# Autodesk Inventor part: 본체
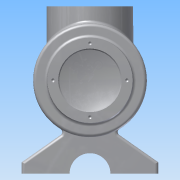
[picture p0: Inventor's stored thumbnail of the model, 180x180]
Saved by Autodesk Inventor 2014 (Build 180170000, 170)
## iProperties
Created: 2017-04
Part Number: 본체
Material: 알루미늄 6061
Document SubType Name: Modeling
Designer: NET
Mass: 1666.1 g
Surface Area: 1068.54 cm^2
Volume: 614.797 cm^3
Density: 2.71 g/cm^3
Appearance: 알루미늄 - 평지
Author: NET
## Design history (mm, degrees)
sketch "스케치1"
  geometry: L1 (-60, -40)-(60, -40); L2 (60, -40)-(60, 40); L3 (60, 40)-(-60, 40); L4 (-60, 40)-(-60, -40); L5 (-60, -40)-(60, 40); L6 (60, -40)-(-60, 40); 1 further point
  constraints: 12 end point, 2 midpoint, 2 parallel, 1 horizontal, 1 perpendicular
  dimensions: "d0" = 120 distance of L3.end L2.end; "d1" = 80 distance of L2.end L1.end
extrude "돌출1" new body sketch "스케치1" distance "d2" = 10; taper "d3" = 0 deg
sketch "스케치2"
  geometry: L1 (60, 0)-(-60, 0) reference; L2 (-60, 0)-(-60, 10) reference; L3 (60, 10)-(-60, 10) reference; L4 (60, 0)-(60, 10) reference; L5 (-60, 10)-(0, 52.012); L6 (-60, 10)-(13.246, 10); L7 (0, 52.012)-(60, 10); 1 further point
  constraints: 6 end point, 1 equal length, 1 horizontal
  dimensions: "d4" = 35 deg angle of L6 L5; "d5" = 35 deg angle of L1 L7
extrude "돌출2" join sketch "스케치2" stored distance "d6" = 80; taper "d7" = 0 deg
sketch "스케치3"
  geometry: C1 r 50 at (0, 82); 1 further point
  constraints: 1 centre point, 1 vertical alignment
  dimensions: "d8" = 100 diameter of C1; "d9" = 82 distance of point (0, 0) C1.centre
extrude "돌출3" join sketch "스케치3" stored distance "d10" = 108; taper "d11" = 0 deg
sketch "스케치4"
  geometry: C1 r 50 at (0, 0) reference; C2 r 37.5 at (0, 0); 1 further point
  constraints: 1 centre point, 1 coincident
  dimensions: "d12" = 75 diameter of C2
extrude "돌출4" join sketch "스케치4" distance "d13" = 12; taper "d14" = 0 deg
sketch "스케치5"
  geometry: L1 (119.5, 66)-(44.5, 66) reference; L2 (32, -54)-(132, -54) reference; L3 (82, 66)-(82, 59); L4 (82, 59)-(82, -54); L5 (82, 59)-(195, 59); L6 (132, -42.336)-(82, -42.336); L7 (82, -54)-(82, -42.336); L8 (132, -42.336)-(132, -54); L9 (82, -54)-(82, -42.336); L10 (132, -54)-(82, -54); 1 further point
  constraints: 16 end point, 4 perpendicular, 2 midpoint, 1 coincident, 1 collinear, 1 horizontal, 1 parallel, 1 point on line
  dimensions: "d18" = 7 distance of L3.start L3.end; "d19" = 90 deg angle of L4 L5; "d20" = 11.66393 distance from line of L2.end L6
revolve "회전1" sketch "스케치5" stored, may be unused: angle "d21" = 90 deg
sketch "스케치6"
  geometry: L1 (119.5, 66)-(44.5, 66) reference; L2 (82, 66)-(82, 59); L3 (82, 59)-(82, -54); L4 (82, 59)-(195, 59); L5 (132, -42.336)-(32, -42.336) reference; L6 (132, -42.336)-(82, -42.336); L7 (82, -54)-(82, -42.336); A1 r 113 centre (82, 59) between (82, -54) and (132, -42.336); 1 further point
  constraints: 10 end point, 2 midpoint, 2 perpendicular, 2 point on circle, 1 centre point, 1 coincident, 1 horizontal, 1 point on line
  dimensions: "d22" = 7 distance of L2.start L2.end; "d23" = 113 radius of A1; "d24" = 90 deg angle of L3 L4
revolve "회전2" sketch "스케치6" stored, may be unused: angle "d25" = 90 deg
sketch "스케치7"
  geometry: C1 r 37.5 at (0, 0) reference; C2 r 27 at (0, 0); 1 further point
  constraints: 1 centre point, 1 coincident
  dimensions: "d26" = 54 diameter of C2
extrude "돌출5" cut sketch "스케치7" distance "d27" = 22; taper "d28" = 0 deg
sketch "스케치8"
  geometry: L1 (55, 44)-(109, 44) reference; L2 (132, -42.336)-(132, 54) reference; L3 (82, 44)-(82, -44); L4 (82, 44)-(122, 44); L5 (122, 44)-(122, -35.916); A1 r 113 centre (82, 59) between (32, -42.336) and (132, -42.336) reference; A2 r 103 centre (82, 59) between (82, -44) and (122, -35.916); 1 further point
  constraints: 6 end point, 2 perpendicular, 2 point on circle, 1 centre point, 1 midpoint, 1 parallel
  dimensions: "d29" = 10 radial gap between concentric circles of A1 A2; "d30" = 40 distance of L3.start L4.end
revolve "회전3" sketch "스케치8" stored, may be unused: angle "d31" = 90 deg
node "작업 평면1"
sketch "스케치13"
  geometry: L1 (50, 54)-(-50, 54) reference; C1 r 38 at (0, 4); 1 further point
  constraints: 1 centre point
  dimensions: "d44" = 76 diameter of C1; "d45" = 50 distance from line of C1.centre L1; "d46" = 70.71068 distance of L1.start C1.centre
extrude "돌출8" join sketch "스케치13" stored distance "d47" = 40; taper "d48" = 0 deg
sketch "스케치14"
  geometry: C1 r 38 at (0, 0) reference; C2 r 27 at (0, 0); 1 further point
  constraints: 1 centre point, 1 coincident
  dimensions: "d49" = 54 diameter of C2
extrude "돌출9" cut sketch "스케치14" distance "d50" = 40; taper "d51" = 0 deg
sketch "스케치15"
  geometry: C1 r 18 at (60, 0); 1 further point
  constraints: 1 centre point, 1 coincident
  dimensions: "d52" = 36 diameter of C1
extrude "돌출10" cut sketch "스케치15" stored distance "d53" = 40; taper "d54" = 0 deg
sketch "스케치18"
  geometry: L1 (60, 40)-(60, -40) reference; L2 (18, 40)-(60, 40) reference; L3 (60, 40)-(60, 20); L4 (60, 20)-(50, 20); L5 (50, 20)-(50, 40); L6 (60, 40)-(50, 40); C1 r 4 at (50, 20); 1 further point
  constraints: 8 end point, 2 perpendicular, 2 point on line, 1 centre point, 1 coincident, 1 collinear
  dimensions: "d69" = 20 distance of L1.start L3.end; "d70" = 10 distance of L3.end L4.end; "d71" = 8 diameter of C1
extrude "돌출12" cut sketch "스케치18" distance "d72" = 6; taper "d73" = 0 deg
sketch "스케치21"
  geometry: L1 (10, 20)-(10, -60) reference; L2 (0, 8)-(10, 8); L3 (10, -8)-(0, -8); L4 (10, 8)-(10, -8); C1 r 4 at (0, 0) reference; A1 r 8 centre (0, 0) between (0, 8) and (0, -8); 1 further point
  constraints: 6 end point, 2 perpendicular, 2 point on circle, 2 point on line, 2 tangent, 1 centre point, 1 coincident
  dimensions: "d76" = 16 diameter of A1
extrude "돌출13" cut sketch "스케치21" distance "d77" = 20; taper "d78" = 0 deg
sketch "스케치22" dims "d79" = 65
  geometry: C1 r 37.5 at (0, 0) reference; 3 further points
  constraints: 1 coincident, 1 horizontal alignment, 2 other
  dimensions: "d80" = 88.20573 distance of point (0, -82) point (-32.5, 0)
hole "구멍2" sketch "스케치22" at (-32.5, 0) diameter "d81" = 3.459; stored, may be unused: countersink angle "d85" = 90 deg, drill point angle "d87" = 118 deg; dims "d82" = 8, "d83" = 4, "d84" = 2, "d86" = 10
sketch "스케치23" dims "d91" = 65
  geometry: C1 r 38 at (0, 0) reference; 3 further points
  constraints: 1 coincident, 1 horizontal alignment, 2 other
  dimensions: "d92" = 32.74523 distance of point (0, 4) point (-32.5, 0)
hole "구멍3" sketch "스케치23" at (-32.5, 0) diameter "d93" = 3.459; stored, may be unused: countersink angle "d97" = 90 deg, drill point angle "d99" = 118 deg; dims "d94" = 8, "d95" = 4, "d96" = 2, "d98" = 10
fillet "모깎기1" dims "d103" = 3
fillet "모깎기2" dims "d104" = 3
chamfer "모따기1" distance "d105" = 1; stored, may be unused: second distance "d106" = 2, angle "d107" = 45 deg
node "작업 평면3"
sketch "스케치24"
  geometry: 3 further points
  constraints: 2 coincident, 1 other
feature "엠보싱1" sketch "스케치24" dims "d0" = 120, "d1" = 80, "d109" = 0.5, "d110" = 0
node "솔리드1"
mirror "대칭1"
mirror "대칭2"
pattern_circular "원형 패턴1" dims angle "d89" = 360 deg
pattern_circular "원형 패턴2" dims angle "d101" = 360 deg
node "투영된 루프1"
other parameters: "d32" = 147
